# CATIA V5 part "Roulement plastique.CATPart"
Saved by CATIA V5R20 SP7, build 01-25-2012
Part number: Roulement plastique axe
Bounding box of the stored display mesh (mm): x -7.49 to 15.31, y -79.76 to -60.593, z 4.057 to 23.225
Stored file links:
  F:\Travaux\Modélisations\CFAO_2011\MMS\MMS_GR2\AA_OK\jboiteux\Catia\Roulement plastique.CATPart
  U:\finthinkmotion\stepper.CATProduct
  F:\Travaux\Modélisations\CFAO_2011\MMS\MMS_GR2\AA_OK\jboiteux\Catia\Part2.CATPart
  F:\Travaux\Modélisations\CFAO_2011\MMS\MMS_GR2\AA_OK\jboiteux\Catia\entretoise pied droit.CATPart
  F:\Travaux\Modélisations\CFAO_2011\MMS\MMS_GR2\AA_OK\jboiteux\Catia\bati.CATPart
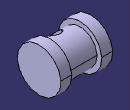
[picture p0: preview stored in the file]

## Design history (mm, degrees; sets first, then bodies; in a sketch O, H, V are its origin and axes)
Parameters
  `rayon roulement` = 9 mm {= External.royontubebati}
  rayontube = 9 mm {= `rayon roulement`}
External parameters (linked from other documents)
  External.royontubebati = 9 mm
Set1
  Plane1: linked copy from another document
  Line1: linked copy from another document
  Plane2: linked copy from another document
  Point1: linked copy from another document
Body1 (main body)
  Sketch1 on Plane1, origin (0, -25.8368, 41.3475), H (1, 0, 0), V (0, 0.848, 0.5299)
    line L1 (-7.49, -52.2845) -> (-7.49, -61.8845)
    line L2 (-7.49, -61.8845) -> (-2.69, -61.8845)
    line L3 (-2.69, -61.8845) -> (-2.69, -59.8845)
    line L4 (-2.69, -59.8845) -> (10.51, -59.8845)
    line L5 (10.51, -59.8845) -> (10.51, -61.8845)
    point P6 (10.51, -61.8845)
    line L6 (10.51, -61.8845) -> (15.31, -61.8845)
    line L7 (15.31, -61.8845) -> (15.31, -52.2845)
    line L8 (15.31, -52.2845) -> (-7.49, -52.2845)
    reference projected line E1 (-9.69, -52.2845) -> (10.31, -52.2845) from Line1
    reference intersected line E2 through (3.91, 0) direction (0, 1) from Plane2
    distance E1 L8 = 0
    distance L7 L1 = 22.8 {= `rayon roulement` *16/5-6mm}
    length L6 = 4.8 {= `rayon roulement` *8/15}
    length L2 = 4.8 {= `rayon roulement` *8/15}
    distance L4 L2 = 2
    distance L8 L2 = 9.6 {= `rayon roulement` *16/15}
    distance E2 L1 = 11.4 {= 8/5*`rayon roulement`  -3mm}
    vertical: L1 V, L3 V, L5 V, L7 V
    horizontal: L2 H, L4 H, L6 H, L8 H
    coincidence: P6 L2
  Shaft1: profile Sketch1, axis Sketch1.L8, angle 360
  Sketch2 on Plane1, origin (0, -25.8368, 41.3475), H (1, 0, 0), V (0, 0.848, 0.5299)
    circle A1 centre (3.91, -52.2845) radius 2.4
    point P1 (3.91, -52.2845)
    reference projected point E1 (3.91, -52.2845) from Point1
    radius A1 = 2.4 {= `rayon roulement` *8/30}
    coincidence: E1 P1
  Pocket1: profile Sketch2, direction (0, 0.5299, -0.848), up to face of Shaft1 from Sketch1.L4, opposite side up to face of Shaft1 from Sketch1.L4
